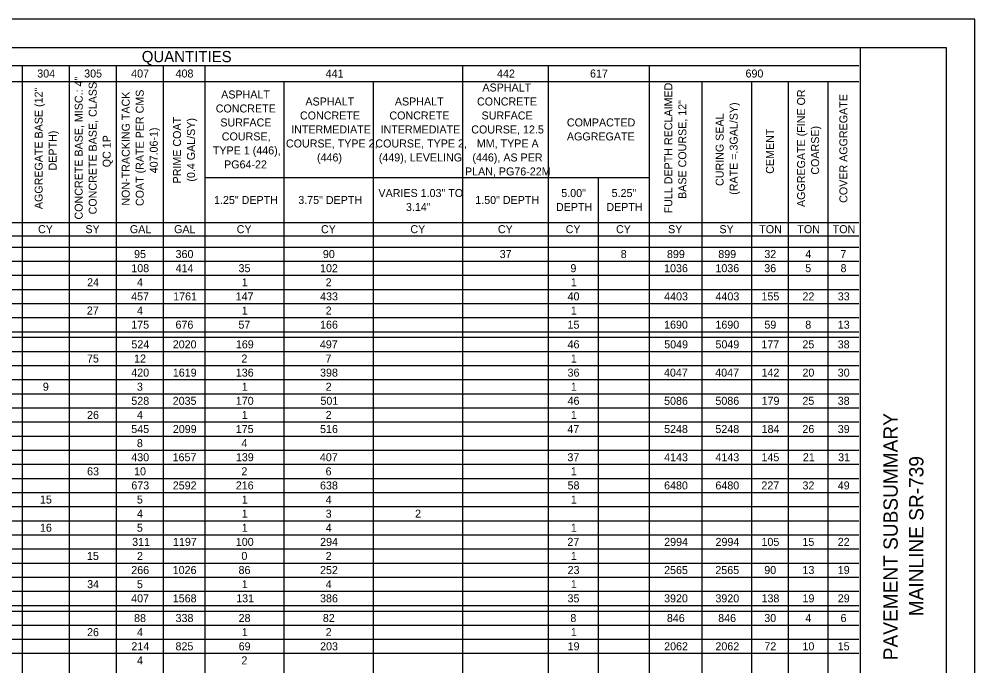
# Model space of a CAD drawing. Extents: x 0 to 34, y 0 to 22.
# Drawn here: x 17.28 to 34, y 10.67 to 22 of the extents above; entities that cross this region are included whole.
import ezdxf

# ---------------------------------------------------------------- set-up
doc = ezdxf.new("R2010")
doc.units = 0
for name, color, linetype in [('SH_Border', 7, 'Continuous'), ('SH_Cut_Line', 7, 'Continuous'), ('SH_Data', 7, 'Continuous'), ('SH_Text', 7, 'Continuous')]:
    doc.layers.add(name, color=color, linetype=linetype)

msp = doc.modelspace()

# ---------------------------------------------------------------- linework, layer by layer
at = {"layer": 'SH_Border'}
msp.add_line((32, 0.5), (32, 21.5), dxfattribs=at)
msp.add_lwpolyline([(1.5, 21.5), (33.5, 21.5), (33.5, 0.5), (1.5, 0.5)], close=True, dxfattribs=at)
at = {"layer": 'SH_Cut_Line'}
msp.add_lwpolyline([(0, 0), (34, 0), (34, 22), (0, 22)], close=True, dxfattribs=at)
at = {"layer": 'SH_Text'}
for p, q in [((1.5, 21.5), (31.971, 21.5)), ((1.5, 21.187), (31.971, 21.187)), ((17.328, 21.187), (17.328, 0.516)), ((18.152, 21.187), (18.152, 0.516)), ((18.975, 21.187), (18.975, 0.516)), ((19.799, 21.187), (19.799, 0.516)), ((20.524, 21.187), (20.524, 0.516)), ((25.036, 21.187), (25.036, 0.516)), ((26.535, 21.187), (26.535, 0.516)), ((28.298, 21.187), (28.298, 0.516)), ((8.368, 20.907), (31.971, 20.907)), ((21.907, 20.907), (21.907, 0.516)), ((23.472, 20.907), (23.472, 0.516)), ((29.22, 20.907), (29.22, 0.516)), ((30.093, 20.907), (30.093, 0.516)), ((30.735, 20.907), (30.735, 0.516)), ((31.427, 20.907), (31.427, 0.516)), ((20.524, 19.227), (28.298, 19.227)), ((27.408, 19.227), (27.408, 0.813)), ((6.524, 18.436), (31.971, 18.436)), ((1.5, 18.206), (31.971, 18.206)), ((1.5, 18.008), (31.971, 18.008)), ((1.5, 17.761), (31.971, 17.761)), ((1.5, 17.514), (31.971, 17.514)), ((1.5, 17.267), (31.971, 17.267)), ((1.5, 17.02), (31.971, 17.02)), ((1.5, 16.773), (31.971, 16.773)), ((1.5, 16.526), (31.971, 16.526)), ((1.5, 16.427), (31.971, 16.427)), ((1.5, 16.18), (31.971, 16.18)), ((1.5, 15.933), (31.971, 15.933)), ((1.5, 15.686), (31.971, 15.686)), ((1.5, 15.439), (31.971, 15.439)), ((1.5, 15.192), (31.971, 15.192)), ((1.5, 14.945), (31.971, 14.945)), ((1.5, 14.698), (31.971, 14.698)), ((1.5, 14.451), (31.971, 14.451)), ((1.5, 14.204), (31.971, 14.204)), ((1.5, 13.956), (31.971, 13.956)), ((1.5, 13.709), (31.971, 13.709)), ((1.5, 13.462), (31.971, 13.462)), ((1.5, 13.215), (31.971, 13.215)), ((1.5, 12.968), (31.971, 12.968)), ((1.5, 12.721), (31.971, 12.721)), ((1.5, 12.474), (31.971, 12.474)), ((1.5, 12.227), (31.971, 12.227)), ((1.5, 11.98), (31.971, 11.98)), ((1.5, 11.733), (31.971, 11.733)), ((1.5, 11.634), (31.971, 11.634)), ((1.5, 11.387), (31.971, 11.387)), ((1.5, 11.14), (31.971, 11.14)), ((1.5, 10.893), (31.971, 10.893))]:
    msp.add_line(p, q, dxfattribs=at)

# ---------------------------------------------------------------- texts
at = {"layer": 'SH_Data'}
for s, p in [('PAVEMENT SUBSUMMARY', (32.65, 10.772)), ('MAINLINE SR-739', (33.1, 11.542))]:
    msp.add_text(s, height=0.25, rotation=90, dxfattribs=at).set_placement(p)
at = {"layer": 'SH_Text'}
for s, height, p in [('QUANTITIES', 0.196, (19.422, 21.246)), ('304', 0.14, (17.594, 20.977)), ('305', 0.14, (18.415, 20.977)), ('407', 0.14, (19.237, 20.977)), ('408', 0.14, (20.014, 20.977)), ('441', 0.14, (22.64, 20.977)), ('442', 0.14, (25.639, 20.977)), ('617', 0.14, (27.266, 20.977)), ('690', 0.14, (29.987, 20.977)), ('ASPHALT ', 0.14, (20.812, 20.61)), ('ASPHALT ', 0.14, (25.383, 20.732)), ('ASPHALT ', 0.14, (22.286, 20.487)), ('ASPHALT ', 0.14, (23.851, 20.487)), ('CONCRETE ', 0.14, (25.288, 20.487)), ('CONCRETE ', 0.14, (20.717, 20.365)), ('SURFACE ', 0.14, (20.797, 20.12)), ('CONCRETE ', 0.14, (22.191, 20.242)), ('CONCRETE ', 0.14, (23.756, 20.242)), ('SURFACE ', 0.14, (25.368, 20.242)), ('COMPACTED ', 0.14, (26.861, 20.12)), ('INTERMEDIATE ', 0.14, (22.037, 19.997)), ('INTERMEDIATE ', 0.14, (23.601, 19.997)), ('COURSE, 12.5 ', 0.14, (25.188, 19.997)), ('COURSE, ', 0.14, (20.823, 19.875)), ('AGGREGATE', 0.14, (26.861, 19.875)), ('TYPE 1 (446), ', 0.14, (20.667, 19.63)), ('COURSE, TYPE 2, ', 0.14, (21.945, 19.752)), ('COURSE, TYPE 2, ', 0.14, (23.51, 19.752)), ('MM, TYPE A ', 0.14, (25.285, 19.752)), ('(446)', 0.14, (22.489, 19.507)), ('(449), LEVELING', 0.14, (23.57, 19.507)), ('(446), AS PER ', 0.14, (25.208, 19.507)), ('PG64-22', 0.14, (20.863, 19.385)), ('PLAN, PG76-22M', 0.14, (25.078, 19.262)), ('1.25" DEPTH', 0.14, (20.687, 18.762)), ('3.75" DEPTH', 0.14, (22.161, 18.762)), ('VARIES 1.03" TO ', 0.14, (23.564, 18.884)), ('1.50" DEPTH', 0.14, (25.258, 18.762)), ('5.00" ', 0.14, (26.763, 18.884)), ('5.25" ', 0.14, (27.644, 18.884)), ('3.14"', 0.14, (24.045, 18.639)), ('DEPTH', 0.14, (26.67, 18.639)), ('DEPTH', 0.14, (27.552, 18.639)), ('CY', 0.14, (17.608, 18.251)), ('SY', 0.14, (18.437, 18.251)), ('GAL', 0.14, (19.214, 18.251)), ('GAL', 0.14, (19.988, 18.251)), ('CY', 0.14, (21.084, 18.251)), ('CY', 0.14, (22.558, 18.251)), ('CY', 0.14, (24.123, 18.251)), ('CY', 0.14, (25.654, 18.251)), ('CY', 0.14, (26.84, 18.251)), ('CY', 0.14, (27.721, 18.251)), ('SY', 0.14, (28.632, 18.251)), ('SY', 0.14, (29.53, 18.251)), ('TON', 0.14, (30.227, 18.251)), ('TON', 0.14, (30.894, 18.251)), ('TON', 0.14, (31.512, 18.251)), ('95', 0.14, (19.288, 17.815)), ('360', 0.14, (20.014, 17.815)), ('90', 0.14, (22.591, 17.815)), ('37', 0.14, (25.685, 17.815)), ('8', 0.14, (27.803, 17.815)), ('899', 0.14, (28.612, 17.815)), ('899', 0.14, (29.51, 17.815)), ('32', 0.14, (30.316, 17.815)), ('4', 0.14, (31.033, 17.815)), ('7', 0.14, (31.646, 17.815)), ('108', 0.14, (19.24, 17.568)), ('414', 0.14, (20.015, 17.568)), ('35', 0.14, (21.116, 17.568)), ('102', 0.14, (22.542, 17.568)), ('9', 0.14, (26.923, 17.568)), ('1036', 0.14, (28.562, 17.568)), ('1036', 0.14, (29.46, 17.568)), ('36', 0.14, (30.315, 17.568)), ('5', 0.14, (31.031, 17.568)), ('8', 0.14, (31.649, 17.568)), ('24', 0.14, (18.467, 17.321)), ('4', 0.14, (19.339, 17.321)), ('1', 0.14, (21.173, 17.321)), ('2', 0.14, (22.64, 17.321)), ('1', 0.14, (26.93, 17.321)), ('457', 0.14, (19.237, 17.074)), ('1761', 0.14, (19.972, 17.074)), ('147', 0.14, (21.065, 17.074)), ('433', 0.14, (22.543, 17.074)), ('40', 0.14, (26.873, 17.074)), ('4403', 0.14, (28.563, 17.074)), ('4403', 0.14, (29.461, 17.074)), ('155', 0.14, (30.266, 17.074)), ('22', 0.14, (30.983, 17.074)), ('33', 0.14, (31.601, 17.074)), ('27', 0.14, (18.462, 16.826)), ('4', 0.14, (19.339, 16.826)), ('1', 0.14, (21.173, 16.826)), ('2', 0.14, (22.64, 16.826)), ('1', 0.14, (26.93, 16.826)), ('175', 0.14, (19.239, 16.579)), ('676', 0.14, (20.013, 16.579)), ('57', 0.14, (21.114, 16.579)), ('166', 0.14, (22.542, 16.579)), ('15', 0.14, (26.872, 16.579)), ('1690', 0.14, (28.562, 16.579)), ('1690', 0.14, (29.46, 16.579)), ('59', 0.14, (30.317, 16.579)), ('8', 0.14, (31.032, 16.579)), ('13', 0.14, (31.601, 16.579)), ('524', 0.14, (19.241, 16.234)), ('2020', 0.14, (19.965, 16.234)), ('169', 0.14, (21.069, 16.234)), ('497', 0.14, (22.539, 16.234)), ('46', 0.14, (26.873, 16.234)), ('5049', 0.14, (28.564, 16.234)), ('5049', 0.14, (29.461, 16.234)), ('177', 0.14, (30.264, 16.234)), ('25', 0.14, (30.982, 16.234)), ('38', 0.14, (31.6, 16.234)), ('75', 0.14, (18.464, 15.986)), ('12', 0.14, (19.289, 15.986)), ('2', 0.14, (21.166, 15.986)), ('7', 0.14, (22.637, 15.986)), ('1', 0.14, (26.93, 15.986)), ('420', 0.14, (19.239, 15.739)), ('1619', 0.14, (19.966, 15.739)), ('136', 0.14, (21.068, 15.739)), ('398', 0.14, (22.542, 15.739)), ('36', 0.14, (26.873, 15.739)), ('4047', 0.14, (28.56, 15.739)), ('4047', 0.14, (29.457, 15.739)), ('142', 0.14, (30.267, 15.739)), ('20', 0.14, (30.983, 15.739)), ('30', 0.14, (31.6, 15.739)), ('9', 0.14, (17.692, 15.492)), ('3', 0.14, (19.338, 15.492)), ('1', 0.14, (21.173, 15.492)), ('2', 0.14, (22.64, 15.492)), ('1', 0.14, (26.93, 15.492)), ('528', 0.14, (19.24, 15.245)), ('2035', 0.14, (19.964, 15.245)), ('170', 0.14, (21.068, 15.245)), ('501', 0.14, (22.549, 15.245)), ('46', 0.14, (26.873, 15.245)), ('5086', 0.14, (28.562, 15.245)), ('5086', 0.14, (29.46, 15.245)), ('179', 0.14, (30.268, 15.245)), ('25', 0.14, (30.982, 15.245)), ('38', 0.14, (31.6, 15.245)), ('26', 0.14, (18.465, 14.998)), ('4', 0.14, (19.339, 14.998)), ('1', 0.14, (21.173, 14.998)), ('2', 0.14, (22.64, 14.998)), ('1', 0.14, (26.93, 14.998)), ('545', 0.14, (19.239, 14.751)), ('2099', 0.14, (19.966, 14.751)), ('175', 0.14, (21.067, 14.751)), ('516', 0.14, (22.542, 14.751)), ('47', 0.14, (26.87, 14.751)), ('5248', 0.14, (28.562, 14.751)), ('5248', 0.14, (29.46, 14.751)), ('184', 0.14, (30.268, 14.751)), ('26', 0.14, (30.982, 14.751)), ('39', 0.14, (31.601, 14.751)), ('8', 0.14, (19.337, 14.504)), ('4', 0.14, (21.167, 14.504)), ('430', 0.14, (19.239, 14.257)), ('1657', 0.14, (19.962, 14.257)), ('139', 0.14, (21.069, 14.257)), ('407', 0.14, (22.539, 14.257)), ('37', 0.14, (26.87, 14.257)), ('4143', 0.14, (28.563, 14.257)), ('4143', 0.14, (29.461, 14.257)), ('145', 0.14, (30.266, 14.257)), ('21', 0.14, (30.99, 14.257)), ('31', 0.14, (31.608, 14.257)), ('63', 0.14, (18.466, 14.01)), ('10', 0.14, (19.288, 14.01)), ('2', 0.14, (21.166, 14.01)), ('6', 0.14, (22.639, 14.01)), ('1', 0.14, (26.93, 14.01)), ('673', 0.14, (19.24, 13.763)), ('2592', 0.14, (19.965, 13.763)), ('216', 0.14, (21.068, 13.763)), ('638', 0.14, (22.542, 13.763)), ('58', 0.14, (26.873, 13.763)), ('6480', 0.14, (28.562, 13.763)), ('6480', 0.14, (29.46, 13.763)), ('227', 0.14, (30.264, 13.763)), ('32', 0.14, (30.983, 13.763)), ('49', 0.14, (31.601, 13.763)), ('15', 0.14, (17.641, 13.516)), ('5', 0.14, (19.337, 13.516)), ('1', 0.14, (21.173, 13.516)), ('4', 0.14, (22.642, 13.516)), ('1', 0.14, (26.93, 13.516)), ('4', 0.14, (19.339, 13.269)), ('1', 0.14, (21.173, 13.269)), ('3', 0.14, (22.64, 13.269)), ('2', 0.14, (24.205, 13.269)), ('16', 0.14, (17.641, 13.022)), ('5', 0.14, (19.337, 13.022)), ('1', 0.14, (21.173, 13.022)), ('4', 0.14, (22.642, 13.022)), ('1', 0.14, (26.93, 13.022)), ('311', 0.14, (19.254, 12.775)), ('1197', 0.14, (19.969, 12.775)), ('100', 0.14, (21.068, 12.775)), ('294', 0.14, (22.544, 12.775)), ('27', 0.14, (26.87, 12.775)), ('2994', 0.14, (28.564, 12.775)), ('2994', 0.14, (29.462, 12.775)), ('105', 0.14, (30.266, 12.775)), ('15', 0.14, (30.982, 12.775)), ('22', 0.14, (31.6, 12.775)), ('15', 0.14, (18.464, 12.528)), ('2', 0.14, (19.338, 12.528)), ('0', 0.14, (21.166, 12.528)), ('2', 0.14, (22.64, 12.528)), ('1', 0.14, (26.93, 12.528)), ('266', 0.14, (19.239, 12.281)), ('1026', 0.14, (19.964, 12.281)), ('86', 0.14, (21.116, 12.281)), ('252', 0.14, (22.542, 12.281)), ('23', 0.14, (26.874, 12.281)), ('2565', 0.14, (28.562, 12.281)), ('2565', 0.14, (29.459, 12.281)), ('90', 0.14, (30.315, 12.281)), ('13', 0.14, (30.983, 12.281)), ('19', 0.14, (31.601, 12.281)), ('34', 0.14, (18.467, 12.034)), ('5', 0.14, (19.337, 12.034)), ('1', 0.14, (21.173, 12.034)), ('4', 0.14, (22.642, 12.034)), ('1', 0.14, (26.93, 12.034)), ('407', 0.14, (19.237, 11.786)), ('1568', 0.14, (19.965, 11.786)), ('131', 0.14, (21.075, 11.786)), ('386', 0.14, (22.542, 11.786)), ('35', 0.14, (26.872, 11.786)), ('3920', 0.14, (28.562, 11.786)), ('3920', 0.14, (29.46, 11.786)), ('138', 0.14, (30.267, 11.786)), ('19', 0.14, (30.984, 11.786)), ('29', 0.14, (31.601, 11.786)), ('88', 0.14, (19.288, 11.441)), ('338', 0.14, (20.014, 11.441)), ('28', 0.14, (21.117, 11.441)), ('82', 0.14, (22.591, 11.441)), ('8', 0.14, (26.922, 11.441)), ('846', 0.14, (28.611, 11.441)), ('846', 0.14, (29.509, 11.441)), ('30', 0.14, (30.315, 11.441)), ('4', 0.14, (31.033, 11.441)), ('6', 0.14, (31.649, 11.441)), ('26', 0.14, (18.465, 11.194)), ('4', 0.14, (19.339, 11.194)), ('1', 0.14, (21.173, 11.194)), ('2', 0.14, (22.64, 11.194)), ('1', 0.14, (26.93, 11.194)), ('214', 0.14, (19.241, 10.946)), ('825', 0.14, (20.013, 10.946)), ('69', 0.14, (21.118, 10.946)), ('203', 0.14, (22.543, 10.946)), ('19', 0.14, (26.874, 10.946)), ('2062', 0.14, (28.563, 10.946)), ('2062', 0.14, (29.46, 10.946)), ('72', 0.14, (30.316, 10.946)), ('10', 0.14, (30.983, 10.946)), ('15', 0.14, (31.6, 10.946)), ('4', 0.14, (19.339, 10.699)), ('2', 0.14, (21.166, 10.699))]:
    msp.add_text(s, height=height, dxfattribs=at).set_placement(p)
for s, p in [('CONCRETE BASE, MISC.: 4" ', (18.389, 18.49)), ('AGGREGATE BASE (12" ', (17.688, 18.672)), ('CONCRETE BASE, CLASS ', (18.634, 18.58)), ('COAT (RATE PER CMS ', (19.457, 18.726)), ('FULL DEPTH RECLAIMED ', (28.706, 18.598)), ('AGGREGATE (FINE OR ', (31.029, 18.709)), ('NON-TRACKING TACK ', (19.212, 18.733)), ('BASE COURSE, 12"', (28.951, 18.851)), ('COVER AGGREGATE', (31.769, 18.782)), ('(RATE =.3GAL/SY)', (29.849, 18.923)), ('PRIME COAT', (20.109, 19.122)), ('(0.4 GAL/SY)', (20.354, 19.154)), ('CURING SEAL', (29.604, 19.078)), ('407.06-1)', (19.702, 19.3)), ('CEMENT', (30.484, 19.291)), ('COARSE)', (31.274, 19.276)), ('DEPTH)', (17.933, 19.349)), ('QC 1P', (18.879, 19.405))]:
    msp.add_text(s, height=0.14, rotation=90, dxfattribs=at).set_placement(p)

doc.saveas('drawing.dxf')
